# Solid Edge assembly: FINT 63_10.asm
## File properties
Title: Zylinder
Author: bmolnar
Template: iso assembly.asm
Last saved by: bmolnar
Revision: 10
Application: Solid Edge
Username: bmolnar
Dokumentum tartalom típus: 1
Document Number: FINT 63/10
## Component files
hrungsstange.par
Profilrohr.par
Platte.par
Kolbenstange.par
Kit_1.par
Kit_2.par
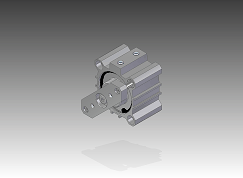
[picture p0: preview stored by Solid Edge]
